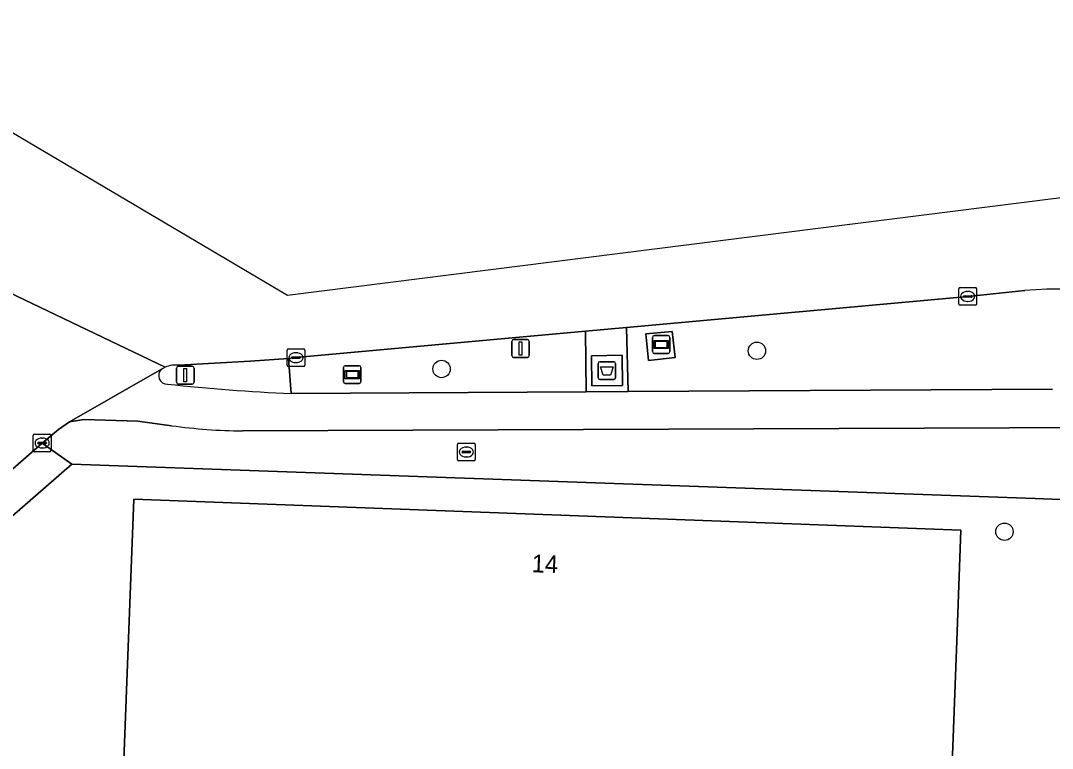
# Model space of a CAD drawing. Extents: x 161347 to 161881, y 382161 to 382804.
# Drawn here: x 161713.8 to 161771.9, y 382546.4 to 382587.4 of the extents above; entities that cross this region are included whole.
import ezdxf

# ---------------------------------------------------------------- set-up
doc = ezdxf.new("R2010")
doc.units = 0
for name, color, linetype in [('IMGEO_Afval_apart_plaats', 7, 'Continuous'), ('IMGEO_Berm_groen', 7, 'Continuous'), ('IMGEO_Boom', 7, 'Continuous'), ('IMGEO_Brandkraan', 7, 'Continuous'), ('IMGEO_Erf', 7, 'Continuous'), ('IMGEO_Fietspad_gesloten', 7, 'Continuous'), ('IMGEO_Kolk', 7, 'Continuous'), ('IMGEO_Lichtmast', 7, 'Continuous'), ('IMGEO_Pand', 7, 'Continuous'), ('IMGEO_Pand_nummerreeks', 7, 'Continuous'), ('IMGEO_Reclamebord', 7, 'Continuous'), ('IMGEO_Rijbaan_lokaal_gesloten', 7, 'Continuous'), ('IMGEO_Verkeerseiland_groen', 7, 'Continuous'), ('IMGEO_Verkeerseiland_open', 7, 'Continuous'), ('IMGEO_Voetpad_gesloten', 7, 'Continuous'), ('IMGEO_Voetpad_open', 7, 'Continuous'), ('IMGEO_Wegwijzer', 7, 'Continuous')]:
    doc.layers.add(name, color=color, linetype=linetype)

msp = doc.modelspace()

# ---------------------------------------------------------------- linework, layer by layer
at = {"layer": 'IMGEO_Afval_apart_plaats'}
for p, q in [((161746.316, 382567.254), (161746.316, 382568.054)), ((161746.316, 382568.054), (161746.316, 382567.254)), ((161746.416, 382568.154), (161747.206, 382568.154)), ((161747.206, 382568.154), (161746.416, 382568.154)), ((161747.306, 382568.054), (161747.306, 382567.254)), ((161747.306, 382567.254), (161747.306, 382568.054)), ((161747.206, 382567.154), (161746.416, 382567.154)), ((161746.416, 382567.154), (161747.206, 382567.154))]:
    msp.add_line(p, q, dxfattribs=at)
msp.add_lwpolyline([(161746.459, 382567.868), (161747.163, 382567.868), (161747.014, 382567.398), (161746.608, 382567.398), (161746.459, 382567.868)], dxfattribs=at)
for centre, start, end in [((161746.416, 382568.054), 90, 180), ((161746.416, 382568.054), 90, 180), ((161747.206, 382568.054), 0, 90), ((161747.206, 382568.054), 360, 90), ((161746.416, 382567.254), 180, 270), ((161746.416, 382567.254), 180, 270), ((161747.206, 382567.254), 270, 0), ((161747.206, 382567.254), 270, 0)]:
    msp.add_arc(centre, 0.1, start, end, dxfattribs=at)
at = {"layer": 'IMGEO_Berm_groen'}
msp.add_lwpolyline([(161770.354, 382572.163), (161767.139, 382571.832), (161747.915, 382570.08), (161748.005, 382566.469), (161771.903, 382566.611)], dxfattribs=at)
msp.add_lwpolyline([(161750.65, 382568.392), (161749.152, 382568.221), (161748.998, 382569.718), (161750.491, 382569.859)], close=True, dxfattribs=at)
msp.add_arc((161772.524, 382544.855), 27.394, 73.73712, 94.54435, dxfattribs=at)
at = {"layer": 'IMGEO_Boom'}
for centre in [(161755.26, 382568.767), (161737.498, 382567.743), (161769.206, 382558.576)]:
    msp.add_circle(centre, 0.489, dxfattribs=at)
at = {"layer": 'IMGEO_Brandkraan'}
for p, q in [((161738.395, 382562.639), (161738.395, 382563.491)), ((161738.47, 382563.565), (161739.322, 382563.565)), ((161738.883, 382563.345), (161738.908, 382563.345)), ((161739.396, 382563.491), (161739.396, 382562.639)), ((161738.654, 382563.059), (161738.654, 382563.071)), ((161739.092, 382563.022), (161738.694, 382563.022)), ((161738.697, 382563.108), (161739.095, 382563.108)), ((161738.906, 382562.785), (161738.881, 382562.785)), ((161739.138, 382563.071), (161739.138, 382563.059)), ((161739.322, 382562.565), (161738.47, 382562.565))]:
    msp.add_line(p, q, dxfattribs=at)
for points in [[(161738.395, 382562.639), (161738.395, 382563.491)], [(161738.47, 382563.565), (161739.322, 382563.565)], [(161739.396, 382563.491), (161739.396, 382562.639)], [(161739.322, 382562.565), (161738.47, 382562.565)]]:
    msp.add_lwpolyline(points, dxfattribs=at)
for centre, radius, start, end in [((161738.472, 382563.489), 0.0765, 91.55205, 178.44795), ((161738.472, 382563.489), 0.0765, 91.55205, 178.44795), ((161739.32, 382563.489), 0.0765, 1.55205, 88.44795), ((161739.32, 382563.489), 0.0765, 1.55205, 88.44795), ((161738.694, 382563.068), 0.0403, 85.87752, 175.75265), ((161738.691, 382563.058), 0.0366, 178.93798, 274.71019), ((161739.095, 382563.065), 0.043, 264.86636, 352.45326), ((161739.099, 382563.07), 0.0386, 1.73085, 96.63898), ((161738.472, 382562.641), 0.0765, 181.55205, 268.44795), ((161738.472, 382562.641), 0.0765, 181.55205, 268.44795), ((161739.32, 382562.641), 0.0765, 271.55205, 358.44795), ((161739.32, 382562.641), 0.0765, 271.55205, 358.44795)]:
    msp.add_arc(centre, radius, start, end, dxfattribs=at)
for centre, major_axis, ratio, start_param, end_param in [((161738.882, 382563.065), (-0.387, 0.002), 0.722429, 4.712389, 7.853982), ((161738.907, 382563.065), (-0.39, 0.002), 0.717154, 1.570796, 4.712389)]:
    msp.add_ellipse(centre, major_axis=major_axis, ratio=ratio, start_param=start_param, end_param=end_param, dxfattribs=at)
at = {"layer": 'IMGEO_Erf'}
for points in [[(161794.971, 382530.118), (161792.241, 382536.131), (161792.378, 382536.972), (161792.323, 382537.821), (161791.654, 382539.638), (161791.061, 382540.405), (161790.328, 382541.011), (161790.189, 382541.423), (161789.107, 382540.979), (161788.094, 382543.265), (161787.424, 382542.968), (161782.001, 382556.605), (161781.188, 382558.978), (161780.231, 382559.421), (161779.298, 382559.715), (161776.187, 382560.249), (161770.93, 382560.454), (161716.681, 382562.374), (161709.058, 382555.75), (161702.444, 382550.002), (161681.121, 382531.471), (161671.366, 382522.817), (161670.351, 382521.638), (161669.529, 382520.317)], [(161719.514, 382543.259), (161720.16, 382560.416), (161766.754, 382558.659), (161766.519, 382552.424), (161766.277, 382545.989)]]:
    msp.add_lwpolyline(points, dxfattribs=at)
at = {"layer": 'IMGEO_Fietspad_gesloten'}
for points in [[(161721.724, 382567.727), (161716.541, 382564.759), (161717.357, 382564.904), (161720.388, 382564.809), (161722.297, 382564.547)], [(161771.903, 382566.611), (161748.005, 382566.469), (161745.652, 382566.455), (161729.038, 382566.356)], [(161726.285, 382564.255), (161774.303, 382564.444)]]:
    msp.add_lwpolyline(points, dxfattribs=at)
for centre, radius, start, end in [((161722.051, 382567.372), 0.483, 132.61348, 270.61161), ((161733.929, 382676.424), 110.176, 263.81352, 267.45559), ((161726.527, 382594.945), 30.691, 262.07718, 269.54741)]:
    msp.add_arc(centre, radius, start, end, dxfattribs=at)
at = {"layer": 'IMGEO_Kolk'}
for p, q in [((161766.638, 382571.404), (161766.638, 382572.256)), ((161766.713, 382572.33), (161767.565, 382572.33)), ((161767.126, 382572.11), (161767.151, 382572.11)), ((161767.639, 382572.256), (161767.639, 382571.404)), ((161766.897, 382571.824), (161766.897, 382571.836)), ((161767.335, 382571.787), (161766.937, 382571.787)), ((161766.94, 382571.873), (161767.338, 382571.873)), ((161767.149, 382571.55), (161767.124, 382571.55)), ((161767.381, 382571.836), (161767.381, 382571.824)), ((161767.565, 382571.33), (161766.713, 382571.33)), ((161728.797, 382567.955), (161728.797, 382568.807)), ((161728.872, 382568.881), (161729.724, 382568.881)), ((161729.285, 382568.661), (161729.31, 382568.661)), ((161729.798, 382568.807), (161729.798, 382567.955)), ((161729.056, 382568.375), (161729.056, 382568.387)), ((161729.494, 382568.338), (161729.096, 382568.338)), ((161729.099, 382568.424), (161729.497, 382568.424)), ((161729.308, 382568.101), (161729.283, 382568.101)), ((161729.54, 382568.387), (161729.54, 382568.375)), ((161729.724, 382567.881), (161728.872, 382567.881)), ((161714.502, 382563.146), (161714.502, 382563.998)), ((161714.577, 382564.072), (161715.429, 382564.072)), ((161715.503, 382563.998), (161715.503, 382563.146)), ((161714.761, 382563.566), (161714.761, 382563.578)), ((161715.199, 382563.529), (161714.801, 382563.529)), ((161714.804, 382563.615), (161715.202, 382563.615)), ((161714.99, 382563.852), (161715.015, 382563.852)), ((161715.245, 382563.578), (161715.245, 382563.566)), ((161715.429, 382563.072), (161714.577, 382563.072)), ((161715.013, 382563.292), (161714.988, 382563.292))]:
    msp.add_line(p, q, dxfattribs=at)
for points in [[(161766.638, 382571.404), (161766.638, 382572.256)], [(161766.713, 382572.33), (161767.565, 382572.33)], [(161767.639, 382572.256), (161767.639, 382571.404)], [(161767.565, 382571.33), (161766.713, 382571.33)], [(161728.797, 382567.955), (161728.797, 382568.807)], [(161728.872, 382568.881), (161729.724, 382568.881)], [(161729.798, 382568.807), (161729.798, 382567.955)], [(161729.724, 382567.881), (161728.872, 382567.881)], [(161714.502, 382563.146), (161714.502, 382563.998)], [(161714.577, 382564.072), (161715.429, 382564.072)], [(161715.503, 382563.998), (161715.503, 382563.146)], [(161715.429, 382563.072), (161714.577, 382563.072)]]:
    msp.add_lwpolyline(points, dxfattribs=at)
for centre, radius, start, end in [((161766.715, 382572.254), 0.0765, 91.55205, 178.44795), ((161766.715, 382572.254), 0.0765, 91.55205, 178.44795), ((161767.563, 382572.254), 0.0765, 1.55205, 88.44795), ((161767.563, 382572.254), 0.0765, 1.55205, 88.44795), ((161766.937, 382571.833), 0.0403, 85.87752, 175.75265), ((161766.934, 382571.823), 0.0366, 178.93798, 274.71019), ((161767.338, 382571.83), 0.043, 264.86636, 352.45326), ((161767.342, 382571.835), 0.0386, 1.73085, 96.63898), ((161766.715, 382571.406), 0.0765, 181.55205, 268.44795), ((161766.715, 382571.406), 0.0765, 181.55205, 268.44795), ((161767.563, 382571.406), 0.0765, 271.55205, 358.44795), ((161767.563, 382571.406), 0.0765, 271.55205, 358.44795), ((161728.874, 382568.805), 0.0765, 91.55205, 178.44795), ((161728.874, 382568.805), 0.0765, 91.55205, 178.44795), ((161729.722, 382568.805), 0.0765, 1.55205, 88.44795), ((161729.722, 382568.805), 0.0765, 1.55205, 88.44795), ((161728.874, 382567.957), 0.0765, 181.55205, 268.44795), ((161728.874, 382567.957), 0.0765, 181.55205, 268.44795), ((161729.096, 382568.384), 0.0403, 85.87752, 175.75265), ((161729.093, 382568.374), 0.0366, 178.93798, 274.71019), ((161729.497, 382568.381), 0.043, 264.86636, 352.45326), ((161729.501, 382568.386), 0.0386, 1.73085, 96.63898), ((161729.722, 382567.957), 0.0765, 271.55205, 358.44795), ((161729.722, 382567.957), 0.0765, 271.55205, 358.44795), ((161714.579, 382563.996), 0.0765, 91.55205, 178.44795), ((161714.579, 382563.996), 0.0765, 91.55205, 178.44795), ((161715.427, 382563.996), 0.0765, 1.55205, 88.44795), ((161715.427, 382563.996), 0.0765, 1.55205, 88.44795), ((161714.801, 382563.575), 0.0403, 85.87752, 175.75265), ((161714.798, 382563.565), 0.0366, 178.93798, 274.71019), ((161715.202, 382563.572), 0.043, 264.86636, 352.45326), ((161715.206, 382563.577), 0.0386, 1.73085, 96.63898), ((161714.579, 382563.148), 0.0765, 181.55205, 268.44795), ((161714.579, 382563.148), 0.0765, 181.55205, 268.44795), ((161715.427, 382563.148), 0.0765, 271.55205, 358.44795), ((161715.427, 382563.148), 0.0765, 271.55205, 358.44795)]:
    msp.add_arc(centre, radius, start, end, dxfattribs=at)
for centre, major_axis, ratio, start_param, end_param in [((161767.125, 382571.83), (-0.387, 0.002), 0.722429, 4.712389, 7.853982), ((161767.15, 382571.83), (-0.39, 0.002), 0.717154, 1.570796, 4.712389), ((161729.284, 382568.381), (-0.387, 0.002), 0.722429, 4.712389, 7.853982), ((161729.309, 382568.381), (-0.39, 0.002), 0.717154, 1.570796, 4.712389), ((161714.989, 382563.572), (-0.387, 0.002), 0.722429, 4.712389, 7.853982), ((161715.014, 382563.572), (-0.39, 0.002), 0.717154, 1.570796, 4.712389)]:
    msp.add_ellipse(centre, major_axis=major_axis, ratio=ratio, start_param=start_param, end_param=end_param, dxfattribs=at)
at = {"layer": 'IMGEO_Lichtmast'}
for p, q in [((161741.452, 382568.498), (161741.452, 382569.298)), ((161741.452, 382569.298), (161741.452, 382568.498)), ((161741.552, 382569.398), (161742.342, 382569.398)), ((161742.342, 382569.398), (161741.552, 382569.398)), ((161742.442, 382569.298), (161742.442, 382568.498)), ((161742.442, 382568.498), (161742.442, 382569.298)), ((161742.342, 382568.398), (161741.552, 382568.398)), ((161741.552, 382568.398), (161742.342, 382568.398)), ((161722.57, 382566.995), (161722.57, 382567.795)), ((161722.57, 382567.795), (161722.57, 382566.995)), ((161722.67, 382567.895), (161723.46, 382567.895)), ((161723.46, 382567.895), (161722.67, 382567.895)), ((161723.56, 382567.795), (161723.56, 382566.995)), ((161723.56, 382566.995), (161723.56, 382567.795)), ((161723.46, 382566.895), (161722.67, 382566.895)), ((161722.67, 382566.895), (161723.46, 382566.895))]:
    msp.add_line(p, q, dxfattribs=at)
for points in [[(161741.872, 382569.273), (161742.022, 382569.273), (161742.022, 382568.523), (161741.872, 382568.523), (161741.872, 382569.273)], [(161722.99, 382567.77), (161723.14, 382567.77), (161723.14, 382567.02), (161722.99, 382567.02), (161722.99, 382567.77)]]:
    msp.add_lwpolyline(points, dxfattribs=at)
for centre, start, end in [((161741.552, 382569.298), 90, 180), ((161741.552, 382569.298), 90, 180), ((161742.342, 382569.298), 0, 90), ((161742.342, 382569.298), 360, 90), ((161741.552, 382568.498), 180, 270), ((161741.552, 382568.498), 180, 270), ((161742.342, 382568.498), 270, 0), ((161742.342, 382568.498), 270, 0), ((161722.67, 382567.795), 90, 180), ((161722.67, 382567.795), 90, 180), ((161723.46, 382567.795), 0, 90), ((161723.46, 382567.795), 360, 90), ((161722.67, 382566.995), 180, 270), ((161722.67, 382566.995), 180, 270), ((161723.46, 382566.995), 270, 0), ((161723.46, 382566.995), 270, 0)]:
    msp.add_arc(centre, 0.1, start, end, dxfattribs=at)
at = {"layer": 'IMGEO_Pand'}
msp.add_lwpolyline([(161750.597, 382534.435), (161754.713, 382535.995), (161755.002, 382541.928), (161761.112, 382541.699), (161766.108, 382541.512), (161766.277, 382545.989), (161766.519, 382552.424), (161766.754, 382558.659), (161720.16, 382560.416), (161719.514, 382543.259), (161724.511, 382543.072), (161752.332, 382542.029), (161752.228, 382539.889), (161750.406, 382539.978), (161748.369, 382539.161), (161749.331, 382536.762), (161734.18, 382530.69), (161735.075, 382528.457), (161740.655, 382530.595), (161743.927, 382531.906)], close=True, dxfattribs=at)
at = {"layer": 'IMGEO_Reclamebord'}
for p, q in [((161749.374, 382568.722), (161749.374, 382569.522)), ((161749.374, 382569.522), (161749.374, 382568.722)), ((161749.474, 382569.622), (161750.264, 382569.622)), ((161750.264, 382569.622), (161749.474, 382569.622)), ((161750.364, 382569.522), (161750.364, 382568.722)), ((161750.364, 382568.722), (161750.364, 382569.522)), ((161750.264, 382568.622), (161749.474, 382568.622)), ((161749.474, 382568.622), (161750.264, 382568.622))]:
    msp.add_line(p, q, dxfattribs=at)
for points in [[(161749.475, 382569.354), (161750.263, 382569.354), (161750.263, 382568.89), (161749.475, 382568.89), (161749.475, 382569.354)], [(161749.54, 382569.289), (161749.54, 382568.955), (161750.198, 382568.955), (161750.198, 382569.289), (161749.54, 382569.289)]]:
    msp.add_lwpolyline(points, dxfattribs=at)
for centre, start, end in [((161749.474, 382569.522), 90, 180), ((161749.474, 382569.522), 90, 180), ((161750.264, 382569.522), 0, 90), ((161750.264, 382569.522), 360, 90), ((161749.474, 382568.722), 180, 270), ((161749.474, 382568.722), 180, 270), ((161750.264, 382568.722), 270, 0), ((161750.264, 382568.722), 270, 0)]:
    msp.add_arc(centre, 0.1, start, end, dxfattribs=at)
at = {"layer": 'IMGEO_Rijbaan_lokaal_gesloten'}
for points in [[(161780.196, 382571.153), (161779.525, 382578.285), (161728.827, 382571.874), (161701.238, 382588.176), (161661.586, 382630.771), (161622.627, 382671.947), (161592.087, 382705.487), (161563.602, 382736.77)], [(161575.378, 382721.548), (161577.619, 382719.049), (161589.767, 382705.692), (161601.665, 382692.722), (161616.607, 382676.142), (161624.391, 382667.348), (161636.242, 382654.182), (161636.579, 382653.807), (161653.899, 382634.564), (161673.989, 382613.712), (161706.007, 382577.787), (161705.643, 382575.646), (161721.925, 382567.837)], [(161707.699, 382557.212), (161708.262, 382557.69), (161711.696, 382560.686), (161715.002, 382563.572), (161715.917, 382564.341), (161716.541, 382564.759), (161721.724, 382567.727), (161721.925, 382567.837), (161705.643, 382575.646)], [(161722.7, 382567.959), (161726.721, 382568.193), (161728.883, 382568.336), (161729.297, 382568.383), (161745.609, 382569.87), (161747.915, 382570.08), (161767.139, 382571.832), (161770.354, 382572.163)]]:
    msp.add_lwpolyline(points, dxfattribs=at)
for centre, radius, start, end in [((161772.524, 382544.855), 27.394, 73.73712, 94.54435), ((161722.54, 382566.454), 1.514, 83.92943, 113.96267)]:
    msp.add_arc(centre, radius, start, end, dxfattribs=at)
at = {"layer": 'IMGEO_Verkeerseiland_groen'}
msp.add_lwpolyline([(161745.609, 382569.87), (161729.297, 382568.383), (161728.883, 382568.336), (161729.038, 382566.356), (161745.652, 382566.455)], close=True, dxfattribs=at)
at = {"layer": 'IMGEO_Verkeerseiland_open'}
for points in [[(161729.038, 382566.356), (161728.883, 382568.336), (161726.721, 382568.193), (161722.7, 382567.959)], [(161721.925, 382567.837), (161721.724, 382567.727)]]:
    msp.add_lwpolyline(points, dxfattribs=at)
for centre, radius, start, end in [((161722.54, 382566.454), 1.514, 83.92943, 113.96267), ((161722.051, 382567.372), 0.483, 132.61348, 270.61161), ((161733.929, 382676.424), 110.176, 263.81352, 267.45559)]:
    msp.add_arc(centre, radius, start, end, dxfattribs=at)
at = {"layer": 'IMGEO_Voetpad_gesloten'}
msp.add_lwpolyline([(161747.663, 382568.513), (161745.938, 382568.492), (161745.959, 382566.795), (161747.684, 382566.816)], close=True, dxfattribs=at)
at = {"layer": 'IMGEO_Voetpad_open'}
for points in [[(161748.005, 382566.469), (161747.915, 382570.08), (161745.609, 382569.87), (161745.652, 382566.455)], [(161749.152, 382568.221), (161750.65, 382568.392), (161750.491, 382569.859), (161748.998, 382569.718)], [(161745.959, 382566.795), (161745.938, 382568.492), (161747.663, 382568.513), (161747.684, 382566.816)], [(161716.681, 382562.374), (161715.002, 382563.572), (161711.696, 382560.686), (161708.262, 382557.69), (161707.699, 382557.212), (161709.058, 382555.75)]]:
    msp.add_lwpolyline(points, close=True, dxfattribs=at)
for points in [[(161722.297, 382564.547), (161720.388, 382564.809), (161717.357, 382564.904), (161716.541, 382564.759), (161715.917, 382564.341), (161715.002, 382563.572), (161716.681, 382562.374), (161770.93, 382560.454), (161776.187, 382560.249), (161779.298, 382559.715), (161780.231, 382559.421), (161781.188, 382558.978), (161782.001, 382556.605), (161789.046, 382556.024)], [(161774.303, 382564.444), (161726.285, 382564.255)]]:
    msp.add_lwpolyline(points, dxfattribs=at)
msp.add_arc((161726.527, 382594.945), 30.691, 262.07718, 269.54741, dxfattribs=at)
at = {"layer": 'IMGEO_Wegwijzer'}
for p, q in [((161731.971, 382567.027), (161731.971, 382567.827)), ((161731.971, 382567.827), (161731.971, 382567.027)), ((161732.071, 382567.927), (161732.861, 382567.927)), ((161732.861, 382567.927), (161732.071, 382567.927)), ((161732.961, 382567.827), (161732.961, 382567.027)), ((161732.961, 382567.027), (161732.961, 382567.827)), ((161732.861, 382566.927), (161732.071, 382566.927)), ((161732.071, 382566.927), (161732.861, 382566.927))]:
    msp.add_line(p, q, dxfattribs=at)
for points in [[(161732.072, 382567.659), (161732.86, 382567.659), (161732.86, 382567.195), (161732.072, 382567.195), (161732.072, 382567.659)], [(161732.137, 382567.594), (161732.137, 382567.26), (161732.795, 382567.26), (161732.795, 382567.594), (161732.137, 382567.594)]]:
    msp.add_lwpolyline(points, dxfattribs=at)
for centre, start, end in [((161732.071, 382567.827), 90, 180), ((161732.071, 382567.827), 90, 180), ((161732.861, 382567.827), 0, 90), ((161732.861, 382567.827), 360, 90), ((161732.071, 382567.027), 180, 270), ((161732.071, 382567.027), 180, 270), ((161732.861, 382567.027), 270, 0), ((161732.861, 382567.027), 270, 0)]:
    msp.add_arc(centre, 0.1, start, end, dxfattribs=at)

# ---------------------------------------------------------------- texts
at = {"layer": 'IMGEO_Pand_nummerreeks'}
msp.add_text('14', height=1, rotation=357.7142, dxfattribs=at).set_placement((161742.559, 382556.296))

doc.saveas('drawing.dxf')
